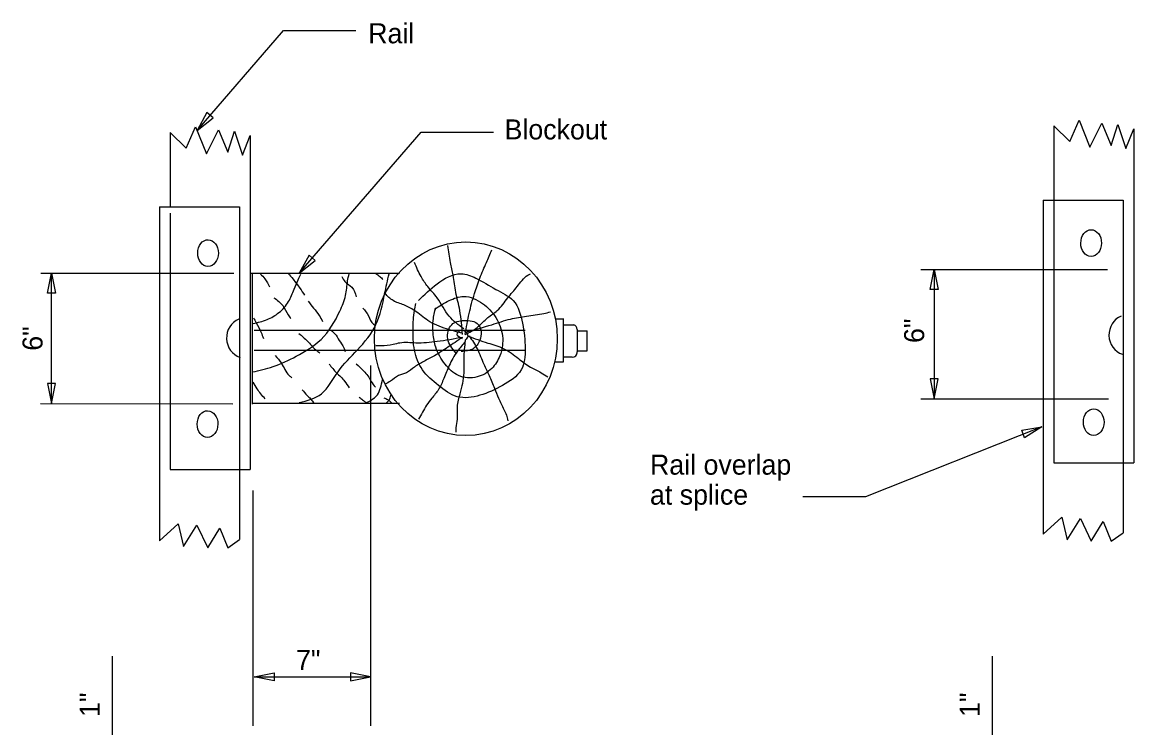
# Model space of a CAD drawing. Extents: x -0.7 to 88.8, y -25.9 to 22.
# Drawn here: x 62.32 to 70.09, y -19.12 to -14.19 of the extents above; entities that cross this region are included whole.
import ezdxf

# ---------------------------------------------------------------- set-up
doc = ezdxf.new("R2010")
doc.units = 0
doc.layers.add('Default', color=7, linetype='Continuous')

msp = doc.modelspace()

# ---------------------------------------------------------------- linework, layer by layer
at = {"layer": 'Default'}
for p, q in [((69.53148042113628, -14.91242783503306), (69.53148042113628, -15.426427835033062)), ((63.350730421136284, -14.959094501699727), (63.350730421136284, -15.473094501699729)), ((63.91081375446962, -14.978927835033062), (63.91081375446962, -17.317094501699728)), ((70.09148042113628, -14.932261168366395), (70.09148042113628, -17.27042783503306)), ((69.45689708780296, -15.431761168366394), (69.45689708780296, -17.768261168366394)), ((69.45689708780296, -15.431761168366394), (70.01689708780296, -15.431761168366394)), ((69.53148042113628, -15.431761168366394), (69.53148042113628, -17.27042783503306)), ((70.01689708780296, -15.431761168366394), (70.01689708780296, -17.75842783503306)), ((63.276147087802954, -15.478427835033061), (63.276147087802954, -17.81492783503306)), ((63.276147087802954, -15.478427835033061), (63.836147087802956, -15.478427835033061)), ((63.350730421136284, -15.522427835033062), (63.350730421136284, -17.317094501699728)), ((63.836147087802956, -15.478427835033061), (63.836147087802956, -17.805094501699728)), ((68.60064708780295, -15.916761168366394), (69.90673042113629, -15.916761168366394)), ((68.69514708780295, -15.916761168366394), (68.69514708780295, -16.49442783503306)), ((62.44564708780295, -15.942427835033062), (63.79464708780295, -15.942427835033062)), ((62.520147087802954, -16.853874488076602), (62.520147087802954, -15.942427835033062)), ((63.90656375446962, -15.942427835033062), (64.95348042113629, -15.942427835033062)), ((63.925147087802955, -16.858427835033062), (63.925147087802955, -15.941761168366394)), ((66.04464708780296, -16.26159450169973), (66.10181375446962, -16.26159450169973)), ((66.10214708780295, -16.56292783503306), (66.10214708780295, -16.260927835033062)), ((66.10214708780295, -16.304261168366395), (66.17331375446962, -16.304261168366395)), ((63.93673042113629, -16.342094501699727), (65.83389708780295, -16.342094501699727)), ((66.05464708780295, -16.356261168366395), (66.05464708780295, -16.356261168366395)), ((66.19681375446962, -16.33792783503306), (66.19714708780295, -16.492261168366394)), ((66.19681375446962, -16.345094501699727), (66.26706375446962, -16.345094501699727)), ((66.26706375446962, -16.485261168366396), (66.26706375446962, -16.345094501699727)), ((63.93673042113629, -16.480427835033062), (65.83389708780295, -16.480427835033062)), ((66.19714708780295, -16.485261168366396), (66.26706375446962, -16.485261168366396)), ((66.04189708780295, -16.56209450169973), (66.10223042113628, -16.56209450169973)), ((66.10223042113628, -16.528761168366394), (66.16173042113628, -16.528761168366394)), ((68.69514708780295, -16.49442783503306), (68.69514708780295, -16.82109450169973)), ((64.75089708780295, -16.58959450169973), (64.75089708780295, -19.109261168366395)), ((62.44389708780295, -16.853761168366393), (63.789647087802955, -16.855761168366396)), ((63.925147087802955, -16.85159450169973), (64.95348042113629, -16.85159450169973)), ((68.60064708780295, -16.82109450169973), (69.91556375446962, -16.82109450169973)), ((63.350730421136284, -17.317094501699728), (63.83489708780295, -17.317094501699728)), ((63.83489708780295, -17.317094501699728), (63.91081375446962, -17.317094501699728)), ((69.53148042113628, -17.27042783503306), (70.01689708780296, -17.27042783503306)), ((70.01689708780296, -17.27042783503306), (70.09148042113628, -17.27042783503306)), ((63.92948042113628, -17.461927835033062), (63.92948042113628, -19.109261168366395)), ((62.944480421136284, -18.622847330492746), (62.944480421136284, -19.27642783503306)), ((69.1012304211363, -18.622847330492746), (69.1012304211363, -19.27642783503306)), ((63.93881375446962, -18.767094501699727), (64.19864708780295, -18.767094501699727)), ((64.19864708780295, -18.767094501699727), (64.75089708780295, -18.767094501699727))]:
    msp.add_line(p, q, dxfattribs=at)
for points in [[(63.53856375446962, -14.944927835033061), (64.14323042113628, -14.245344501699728), (64.65014708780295, -14.245344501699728)], [(63.350730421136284, -14.959094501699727), (63.46314708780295, -15.06792783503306), (63.52848042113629, -14.919594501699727), (63.60323042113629, -15.10742783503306), (63.687147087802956, -14.939427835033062), (63.75248042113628, -15.097427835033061), (63.79914708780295, -14.949261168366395), (63.855147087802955, -15.117261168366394), (63.91081375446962, -14.978927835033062)], [(69.53148042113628, -14.91242783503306), (69.64389708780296, -15.021261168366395), (69.70923042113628, -14.872927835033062), (69.78389708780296, -15.060761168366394), (69.86789708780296, -14.892761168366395), (69.93323042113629, -15.050761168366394), (69.97989708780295, -14.902594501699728), (70.03589708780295, -15.070594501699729), (70.09148042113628, -14.932261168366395)], [(64.25306375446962, -15.942427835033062), (65.10631375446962, -14.955344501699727), (65.61323042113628, -14.955344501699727)], [(69.44864708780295, -17.017677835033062), (68.21523042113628, -17.507927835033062), (67.77589708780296, -17.507927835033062)], [(69.45689708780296, -17.768261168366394), (69.58789708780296, -17.649761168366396), (69.62523042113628, -17.807761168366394), (69.71856375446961, -17.65942783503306), (69.79331375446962, -17.817761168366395), (69.87723042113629, -17.679261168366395), (69.93323042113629, -17.817761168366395), (70.01689708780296, -17.75842783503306)], [(63.276147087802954, -17.81492783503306), (63.407147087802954, -17.69642783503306), (63.44456375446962, -17.85442783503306), (63.53781375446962, -17.706261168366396), (63.61256375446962, -17.864427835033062), (63.696480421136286, -17.725927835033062), (63.75248042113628, -17.864427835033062), (63.836147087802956, -17.805094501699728)]]:
    msp.add_lwpolyline(points, dxfattribs=at)
for points in [[(63.60710477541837, -14.819683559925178), (63.53856375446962, -14.944927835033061), (63.650003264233, -14.855679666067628)], [(64.32160477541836, -15.817183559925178), (64.25306375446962, -15.942427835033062), (64.36450326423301, -15.853179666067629)], [(68.66714492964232, -16.056761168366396), (68.69514492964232, -15.916761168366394), (68.72314492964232, -16.056761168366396)], [(62.49199038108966, -16.082427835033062), (62.519990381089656, -15.942427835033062), (62.547990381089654, -16.082427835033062)], [(62.492147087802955, -16.713874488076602), (62.520147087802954, -16.853874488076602), (62.54814708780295, -16.713874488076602)], [(68.66714708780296, -16.68109450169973), (68.69514708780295, -16.82109450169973), (68.72314708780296, -16.68109450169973)], [(69.30791152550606, -17.04170909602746), (69.44864708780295, -17.017677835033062), (69.32798013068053, -17.09398959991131)], [(64.07881375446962, -18.79509450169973), (63.93881375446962, -18.767094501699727), (64.07881375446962, -18.73909450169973)], [(64.61089708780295, -18.79510349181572), (64.75089708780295, -18.767103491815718), (64.61089708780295, -18.73910349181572)]]:
    msp.add_lwpolyline(points, close=True, dxfattribs=at)
for centre, major_axis, ratio in [((69.79326953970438, -15.732354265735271), (0.0004644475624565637, 0.093636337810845), 0.7737824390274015), ((63.61518889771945, -15.802543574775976), (0.0004644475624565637, 0.093636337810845), 0.7737824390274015), ((65.41861513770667, -16.401902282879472), (1.918312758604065e-16, 0.6771863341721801), 0.9445438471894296), ((63.61150573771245, -16.99866138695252), (0.0004644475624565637, 0.093636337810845), 0.7737824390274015), ((69.81111869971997, -16.98506345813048), (0.0004644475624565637, 0.093636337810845), 0.7737824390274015)]:
    msp.add_ellipse(centre, major_axis=major_axis, ratio=ratio, dxfattribs=at)
for centre, major_axis, ratio, start_param, end_param in [((70.05154969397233, -16.37442590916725), (-2.2745364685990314e-17, -0.1414404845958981), 0.9445438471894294, 3.514867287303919, 5.984065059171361), ((63.87847437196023, -16.396522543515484), (-2.2745364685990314e-17, -0.1414404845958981), 0.9445438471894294, 3.514867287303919, 5.984065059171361), ((66.16893768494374, -16.333768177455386), (-4.793224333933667e-18, -0.0298063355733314), 0.9445438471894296, 1.4313513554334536, 2.9870135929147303), ((66.1667085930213, -16.496978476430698), (-5.240425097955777e-18, -0.03258722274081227), 0.9445438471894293, 6.0937818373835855, 8.00033796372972)]:
    msp.add_ellipse(centre, major_axis=major_axis, ratio=ratio, start_param=start_param, end_param=end_param, dxfattribs=at)
for points in [[(65.39523042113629, -16.372261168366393), (65.37648042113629, -16.204261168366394), (65.34856375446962, -16.075761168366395), (65.32981375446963, -15.957261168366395), (65.31123042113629, -15.868261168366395), (65.29256375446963, -15.749761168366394)], [(65.41389708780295, -16.372261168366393), (65.44181375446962, -16.224094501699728), (65.4792304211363, -16.085594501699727), (65.51656375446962, -15.976927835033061), (65.56323042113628, -15.868261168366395), (65.60048042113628, -15.779427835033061)], [(65.40456375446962, -16.332761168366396), (65.30189708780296, -16.243761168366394), (65.21781375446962, -16.11542783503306), (65.15248042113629, -16.036261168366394), (65.10581375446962, -15.967094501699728), (65.05914708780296, -15.868261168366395)], [(63.92556375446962, -16.634094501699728), (64.06964708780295, -16.596594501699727), (64.23256375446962, -16.523761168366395), (64.40581375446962, -16.40642783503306), (64.53739708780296, -16.207594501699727), (64.57706375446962, -16.099094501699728), (64.59173042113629, -15.997427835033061), (64.60206375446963, -15.946594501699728)], [(63.929730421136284, -16.295927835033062), (64.02789708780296, -16.267261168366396), (64.11139708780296, -16.218594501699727), (64.17823042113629, -16.14109450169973), (64.21789708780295, -16.054927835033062), (64.24498042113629, -15.988594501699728), (64.26381375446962, -15.94892783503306)], [(63.981897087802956, -15.94892783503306), (64.01323042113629, -15.981927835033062), (64.04464708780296, -16.03942783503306)], [(64.17614708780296, -15.94442783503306), (64.20956375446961, -15.984261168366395), (64.25756375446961, -16.04842783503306), (64.29098042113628, -16.09692783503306)], [(64.25339708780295, -16.84859450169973), (64.40789708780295, -16.786761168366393), (64.52481375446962, -16.63192783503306), (64.66056375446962, -16.47942783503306), (64.79006375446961, -16.302594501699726), (64.85064708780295, -16.08809450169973), (64.88189708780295, -15.946594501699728)], [(64.55206375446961, -15.966594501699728), (64.57289708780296, -16.00192783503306), (64.62089708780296, -16.041594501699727), (64.65223042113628, -16.10809450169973)], [(64.78798042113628, -15.94442783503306), (64.81723042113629, -15.966594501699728), (64.83806375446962, -15.98642783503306)], [(65.08723042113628, -16.13509450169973), (65.21781375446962, -16.01659450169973), (65.38581375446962, -15.94742783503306), (65.48848042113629, -15.976927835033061), (65.62856375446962, -16.05609450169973), (65.74989708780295, -16.13509450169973), (65.81514708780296, -16.293261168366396), (65.83389708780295, -16.471094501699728), (65.80589708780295, -16.619261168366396), (65.67523042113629, -16.72792783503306), (65.51656375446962, -16.79709450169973), (65.35789708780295, -16.807094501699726), (65.22723042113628, -16.72792783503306), (65.11514708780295, -16.619261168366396), (65.05914708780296, -16.48092783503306), (65.04981375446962, -16.332761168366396), (65.05914708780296, -16.204261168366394), (65.06856375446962, -16.154761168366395)], [(65.41389708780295, -16.372261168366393), (65.49781375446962, -16.322761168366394), (65.57256375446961, -16.253594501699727), (65.63789708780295, -16.204261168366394), (65.71248042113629, -16.11542783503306), (65.77789708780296, -16.036261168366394), (65.85256375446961, -15.957261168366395), (65.87114708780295, -15.94742783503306)], [(65.39523042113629, -16.36242783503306), (65.28323042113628, -16.332761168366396), (65.15248042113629, -16.27342783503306), (65.05914708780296, -16.204261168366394), (64.98456375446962, -16.164761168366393), (64.90989708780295, -16.13509450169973), (64.85389708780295, -16.085594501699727)], [(64.07589708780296, -16.114594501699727), (64.13856375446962, -16.16992783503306), (64.17614708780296, -16.23409450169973), (64.1949804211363, -16.260594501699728)], [(64.31606375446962, -16.138927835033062), (64.35364708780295, -16.187594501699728), (64.39331375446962, -16.23842783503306), (64.41623042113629, -16.280427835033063)], [(65.19923042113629, -16.194261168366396), (65.30189708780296, -16.13509450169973), (65.40456375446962, -16.105427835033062), (65.53514708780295, -16.154761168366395), (65.62856375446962, -16.253594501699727), (65.67523042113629, -16.38209450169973), (65.65648042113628, -16.52042783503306), (65.60048042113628, -16.60942783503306), (65.49781375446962, -16.66859450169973), (65.36723042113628, -16.658761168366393), (65.27381375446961, -16.579761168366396), (65.20848042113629, -16.461261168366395), (65.18989708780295, -16.36242783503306), (65.18989708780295, -16.27342783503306), (65.20848042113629, -16.184594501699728)], [(64.69814708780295, -16.187594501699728), (64.73789708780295, -16.24059450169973), (64.77331375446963, -16.300261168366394), (64.78589708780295, -16.307094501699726)], [(65.42323042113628, -16.352427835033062), (65.60048042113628, -16.30309450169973), (65.73123042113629, -16.26359450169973), (65.84323042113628, -16.243761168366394), (65.96456375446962, -16.224094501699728), (66.01123042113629, -16.214094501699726)], [(63.933897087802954, -16.256094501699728), (63.95273042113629, -16.289261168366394), (63.986147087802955, -16.357761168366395), (64.00289708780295, -16.399761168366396)], [(65.34856375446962, -16.500761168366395), (65.29256375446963, -16.40192783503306), (65.32048042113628, -16.30309450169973), (65.40456375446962, -16.27342783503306), (65.50723042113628, -16.30309450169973), (65.51656375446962, -16.411761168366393), (65.46989708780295, -16.471094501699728), (65.38581375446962, -16.490761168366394)], [(64.25131375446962, -16.364427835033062), (64.30981375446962, -16.41742783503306), (64.36823042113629, -16.47942783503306), (64.39748042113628, -16.499261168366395)], [(64.47264708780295, -16.340094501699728), (64.50189708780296, -16.366761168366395), (64.53323042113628, -16.413094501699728), (64.56448042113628, -16.46392783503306), (64.57498042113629, -16.49042783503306)], [(65.39523042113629, -16.391927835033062), (65.21781375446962, -16.421761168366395), (65.06856375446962, -16.431427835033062), (64.95656375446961, -16.431427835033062), (64.90989708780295, -16.44142783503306), (64.82581375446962, -16.451261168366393), (64.78848042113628, -16.451261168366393)], [(65.39523042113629, -16.391927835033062), (65.29256375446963, -16.461261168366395), (65.19923042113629, -16.52042783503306), (65.12456375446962, -16.55992783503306), (65.05914708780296, -16.59942783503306), (65.00314708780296, -16.639094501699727), (64.94714708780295, -16.658761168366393), (64.89114708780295, -16.698427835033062), (64.85389708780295, -16.718094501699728)], [(65.39523042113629, -16.40192783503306), (65.35789708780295, -16.372261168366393), (65.38581375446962, -16.34259450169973), (65.43248042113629, -16.38209450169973), (65.41389708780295, -16.411761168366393)], [(65.43248042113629, -16.38209450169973), (65.57256375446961, -16.431427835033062), (65.68456375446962, -16.471094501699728), (65.78723042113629, -16.540261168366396), (65.87114708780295, -16.59942783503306), (65.94589708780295, -16.639094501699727), (65.99256375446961, -16.66859450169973)], [(65.44181375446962, -16.38209450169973), (65.49781375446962, -16.471094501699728), (65.54448042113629, -16.579761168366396), (65.58189708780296, -16.658761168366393), (65.61923042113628, -16.747761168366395), (65.64714708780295, -16.816927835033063), (65.68456375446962, -16.89592783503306), (65.70314708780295, -16.93559450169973), (65.71248042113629, -16.97509450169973)], [(65.41389708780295, -16.421761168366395), (65.35789708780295, -16.490761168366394), (65.30189708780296, -16.58959450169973), (65.26448042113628, -16.678594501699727), (65.22723042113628, -16.757594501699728), (65.18056375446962, -16.816927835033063), (65.14323042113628, -16.866261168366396), (65.11514708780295, -16.915761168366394), (65.08723042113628, -16.965094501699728)], [(65.41389708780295, -16.411761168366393), (65.40456375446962, -16.540261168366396), (65.40456375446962, -16.639094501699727), (65.37648042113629, -16.787261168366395), (65.35789708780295, -16.876261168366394), (65.35789708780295, -16.925594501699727), (65.35789708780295, -16.965094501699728), (65.34856375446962, -17.024427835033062), (65.34856375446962, -17.054094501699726)], [(64.08431375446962, -16.519261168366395), (64.12806375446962, -16.572261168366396), (64.18239708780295, -16.658427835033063), (64.20123042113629, -16.673927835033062)], [(64.46223042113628, -16.57892783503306), (64.51448042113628, -16.640761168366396), (64.57081375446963, -16.698261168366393), (64.60206375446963, -16.744761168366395)], [(64.65223042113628, -16.576594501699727), (64.70448042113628, -16.62759450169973), (64.73364708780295, -16.660594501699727), (64.75664708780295, -16.70042783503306), (64.78589708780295, -16.740261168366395)], [(64.01531375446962, -16.822094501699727), (63.98406375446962, -16.786761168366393), (63.95898042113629, -16.751427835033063), (63.929730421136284, -16.70492783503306)], [(64.7232304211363, -16.850761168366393), (64.75664708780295, -16.830927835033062), (64.80048042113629, -16.793261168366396), (64.82139708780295, -16.744761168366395), (64.83598042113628, -16.687261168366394)], [(64.27431375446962, -16.757927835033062), (64.30773042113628, -16.797761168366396), (64.33273042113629, -16.822094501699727), (64.34948042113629, -16.844261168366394), (64.35573042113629, -16.850761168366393)], [(64.86314708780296, -16.850761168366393), (64.88189708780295, -16.830927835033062), (64.89448042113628, -16.79559450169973)], [(64.67314708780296, -16.811094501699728), (64.69606375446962, -16.828761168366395), (64.72531375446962, -16.850761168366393)], [(64.84431375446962, -16.815427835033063), (64.87156375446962, -16.826594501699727), (64.90073042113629, -16.85309450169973)]]:
    msp.add_spline(points, degree=3, dxfattribs=at)

# ---------------------------------------------------------------- texts
for s, p in [('Rail ', (64.73550107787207, -14.334861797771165)), ('Blockout', (65.68939020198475, -15.007126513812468)), ('Rail overlap', (66.70687193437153, -17.35240595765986)), ('at splice', (66.70687193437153, -17.562405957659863)), ('7"', (64.23101384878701, -18.71873325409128))]:
    msp.add_text(s, height=0.13999999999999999, dxfattribs=at).set_placement(p)
for s, p in [('6" ', (62.45726325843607, -16.485324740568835)), ('6" ', (68.62493405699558, -16.43101441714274)), ('1" ', (62.85698822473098, -19.04704357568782)), ('1" ', (69.01373822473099, -19.04704357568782))]:
    msp.add_text(s, height=0.13999999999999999, rotation=89.99999999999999, dxfattribs=at).set_placement(p)

doc.saveas('drawing.dxf')
